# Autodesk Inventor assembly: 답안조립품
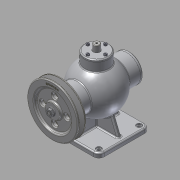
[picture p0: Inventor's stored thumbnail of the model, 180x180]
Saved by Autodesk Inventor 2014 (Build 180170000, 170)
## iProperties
Created: 2015-10
Part Number: 답안조립품
Document SubType Name: Assembly
Designer: youjin18
Author: youjin18
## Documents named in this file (19)
- C:\Users\youjin18\Desktop\451010V1013\답안조립품.iam
- C:\Users\youjin18\Desktop\451010V1013\본체.ipt
- C:\Users\youjin18\Desktop\451010V1013\뒤커버.ipt
- C:\Users\youjin18\Desktop\451010V1013\볼트 M4 x 16.ipt
- C:\Users\youjin18\Desktop\451010V1013\앞커버.ipt
- C:\Users\youjin18\Desktop\451010V1013\상부커버.ipt
- C:\Users\youjin18\Desktop\451010V1013\볼트 M 4 x 12.ipt
- C:\Users\youjin18\Desktop\451010V1013\오일실 15 30 7.ipt
- C:\Users\youjin18\Desktop\451010V1013\베어링- 6202.ipt
- KS B 2023 - 6202 - 15 x 35 x 11 - 7.8.ipt
- C:\Users\youjin18\Desktop\451010V1013\편심축.ipt
- C:\Users\youjin18\Desktop\451010V1013\부시.ipt
- C:\Users\youjin18\Desktop\451010V1013\멈춤링- 35x1.6.ipt
- KS B 1336 - 35x1.6.ipt
- C:\Users\youjin18\Desktop\451010V1013\멈춤링- 15 x 1.ipt
- C:\Users\youjin18\Desktop\451010V1013\키 4 x 4 x 12.ipt
- C:\Users\youjin18\Desktop\451010V1013\V-벨트풀리.ipt
- C:\Users\youjin18\Desktop\451010V1013\슬라이드.ipt
- C:\Users\youjin18\Desktop\451010V1013\너트 M8.ipt
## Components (16 placed, 5 different names)
1. KS B 2023 - 6202 - 15 x 35 x 11 - 7.8:1 — 각도:2
2. KS B 2023 - 6202 - 15 x 35 x 11 - 7.8:2 — 각도:1
3. KS B 1336 - 35x1.6:1
4. V-벨트풀리:1 — 플러쉬:1
5. ISO 4762 M4 x 16:1
6. ISO 4762 M4 x 16:2
7. ISO 4762 M4 x 16:3
8. ISO 4762 M4 x 16:4
9. ISO 4762 M4 x 16:5
10. ISO 4762 M4 x 16:6
11. ISO 4762 M4 x 16:7
12. ISO 4762 M4 x 16:8
13. KS B 1021 - 에 따름 ISO 1207 - 미터 A  M 4 x 12:1
14. KS B 1021 - 에 따름 ISO 1207 - 미터 A  M 4 x 12:2
15. KS B 1021 - 에 따름 ISO 1207 - 미터 A  M 4 x 12:3
16. KS B 1021 - 에 따름 ISO 1207 - 미터 A  M 4 x 12:4
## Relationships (3: Angle 2, Flush 1)
- 플러쉬:1 [Flush]: V-벨트풀리:1
- 각도:1 [Angle]: KS B 2023 - 6202 - 15 x 35 x 11 - 7.8:2
- 각도:2 [Angle]: KS B 2023 - 6202 - 15 x 35 x 11 - 7.8:1
